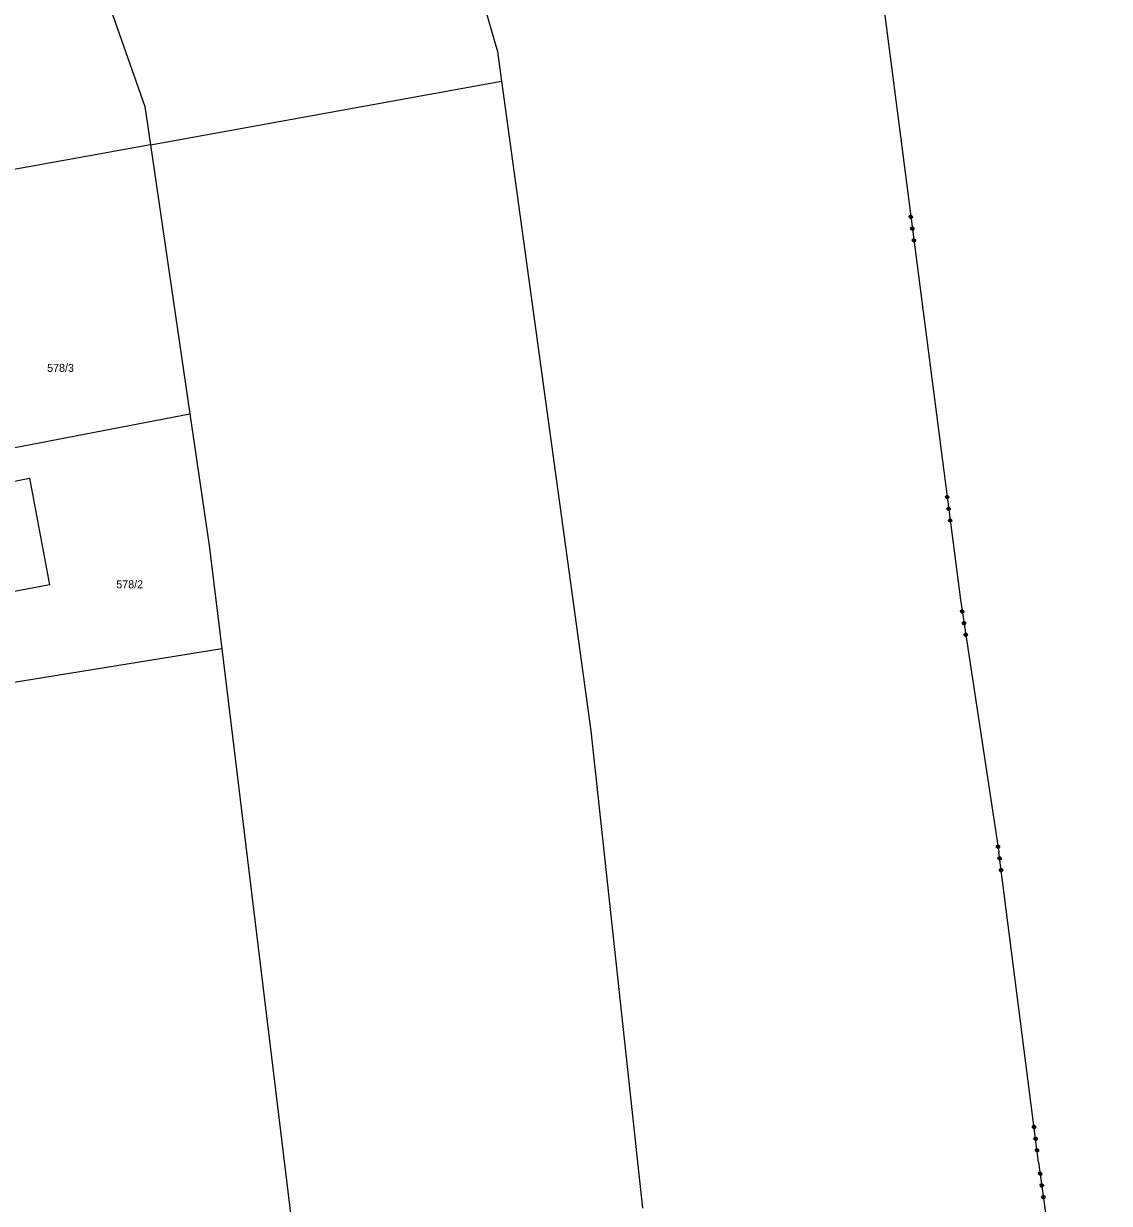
# Model space of a CAD drawing. Extents: x -757994 to -755874, y -1047691 to -1046119.
# Drawn here: x -756280.8 to -756165.6, y -1047301.2 to -1047176 of the extents above; entities that cross this region are included whole.
import ezdxf

# ---------------------------------------------------------------- set-up
doc = ezdxf.new("R2010")
doc.units = 0
doc.layers.add('katastrální mapa', color=7, linetype='Continuous')

msp = doc.modelspace()

# ---------------------------------------------------------------- linework, layer by layer
at = {"layer": 'katastrální mapa'}
for p, q in [((-756190.66, -1047165.51), (-756181.38, -1047237.16)), ((-756273.16, -1047169.96), (-756267.97, -1047184.79)), ((-756233.22, -1047169.59), (-756230.54, -1047178.96)), ((-756230.54, -1047178.96), (-756230.11, -1047182.09)), ((-756267.38, -1047188.84), (-756230.11, -1047182.09)), ((-756230.11, -1047182.09), (-756220.62, -1047251.06)), ((-756267.97, -1047184.79), (-756267.38, -1047188.84)), ((-756267.38, -1047188.84), (-756306.5, -1047195.93)), ((-756267.38, -1047188.84), (-756263.18, -1047217.41)), ((-756305.29, -1047225.5), (-756263.18, -1047217.41)), ((-756263.18, -1047217.41), (-756261.14, -1047231.38)), ((-756299.85, -1047228), (-756280.23, -1047224.25)), ((-756280.23, -1047224.25), (-756278.1, -1047235.56)), ((-756261.14, -1047231.38), (-756259.8, -1047242.35)), ((-756278.1, -1047235.56), (-756283.5, -1047236.59)), ((-756181.38, -1047237.16), (-756177.32, -1047263.94)), ((-756259.8, -1047242.35), (-756308.79, -1047250.3)), ((-756259.8, -1047242.35), (-756246.38, -1047352.4)), ((-756220.62, -1047251.06), (-756215.14, -1047301.74)), ((-756173.09, -1047296.85), (-756177.32, -1047263.94)), ((-756173.09, -1047296.85), (-756165.57, -1047351.39))]:
    msp.add_line(p, q, dxfattribs=at)
for points in [[(-756186.48, -1047196.55), (-756186.56, -1047196.65), (-756186.69, -1047196.67), (-756186.8, -1047196.59), (-756186.82, -1047196.45), (-756186.74, -1047196.35), (-756186.6, -1047196.33), (-756186.5, -1047196.41), (-756186.48, -1047196.55), (-756186.5, -1047196.55), (-756186.51, -1047196.43), (-756186.56, -1047196.4), (-756186.53, -1047196.6), (-756186.57, -1047196.63), (-756186.6, -1047196.36), (-756186.64, -1047196.37), (-756186.61, -1047196.63), (-756186.65, -1047196.64), (-756186.68, -1047196.38), (-756186.72, -1047196.38), (-756186.69, -1047196.65), (-756186.73, -1047196.63), (-756186.76, -1047196.41), (-756186.79, -1047196.45), (-756186.78, -1047196.59)], [(-756186.32, -1047197.79), (-756186.4, -1047197.9), (-756186.53, -1047197.91), (-756186.64, -1047197.83), (-756186.66, -1047197.7), (-756186.58, -1047197.59), (-756186.44, -1047197.57), (-756186.34, -1047197.66), (-756186.32, -1047197.79), (-756186.34, -1047197.79), (-756186.35, -1047197.67), (-756186.4, -1047197.63), (-756186.37, -1047197.83), (-756186.41, -1047197.88), (-756186.44, -1047197.6), (-756186.48, -1047197.6), (-756186.45, -1047197.88), (-756186.49, -1047197.89), (-756186.52, -1047197.61), (-756186.56, -1047197.61), (-756186.53, -1047197.89), (-756186.57, -1047197.86), (-756186.6, -1047197.66), (-756186.63, -1047197.7), (-756186.62, -1047197.82)], [(-756186.16, -1047199.03), (-756186.24, -1047199.14), (-756186.37, -1047199.16), (-756186.48, -1047199.08), (-756186.5, -1047198.94), (-756186.41, -1047198.84), (-756186.28, -1047198.82), (-756186.17, -1047198.9), (-756186.16, -1047199.03), (-756186.18, -1047199.02), (-756186.19, -1047198.9), (-756186.24, -1047198.87), (-756186.21, -1047199.06), (-756186.25, -1047199.11), (-756186.28, -1047198.85), (-756186.32, -1047198.85), (-756186.29, -1047199.11), (-756186.33, -1047199.12), (-756186.36, -1047198.86), (-756186.4, -1047198.86), (-756186.37, -1047199.12), (-756186.41, -1047199.1), (-756186.44, -1047198.9), (-756186.47, -1047198.93), (-756186.46, -1047199.05)], [(-756182.63, -1047226.3), (-756182.71, -1047226.4), (-756182.84, -1047226.42), (-756182.95, -1047226.34), (-756182.97, -1047226.2), (-756182.88, -1047226.1), (-756182.75, -1047226.08), (-756182.64, -1047226.16), (-756182.63, -1047226.3), (-756182.64, -1047226.3), (-756182.66, -1047226.19), (-756182.7, -1047226.15), (-756182.68, -1047226.35), (-756182.72, -1047226.38), (-756182.75, -1047226.12), (-756182.79, -1047226.12), (-756182.76, -1047226.38), (-756182.79, -1047226.39), (-756182.83, -1047226.13), (-756182.87, -1047226.14), (-756182.83, -1047226.4), (-756182.88, -1047226.38), (-756182.9, -1047226.17), (-756182.94, -1047226.21), (-756182.92, -1047226.34)], [(-756182.46, -1047227.54), (-756182.55, -1047227.65), (-756182.68, -1047227.66), (-756182.79, -1047227.58), (-756182.8, -1047227.45), (-756182.72, -1047227.34), (-756182.59, -1047227.33), (-756182.48, -1047227.41), (-756182.46, -1047227.54), (-756182.48, -1047227.54), (-756182.5, -1047227.42), (-756182.55, -1047227.39), (-756182.52, -1047227.58), (-756182.55, -1047227.63), (-756182.59, -1047227.35), (-756182.63, -1047227.36), (-756182.59, -1047227.63), (-756182.63, -1047227.64), (-756182.67, -1047227.36), (-756182.71, -1047227.37), (-756182.67, -1047227.64), (-756182.72, -1047227.61), (-756182.74, -1047227.41), (-756182.78, -1047227.46), (-756182.76, -1047227.57)], [(-756182.3, -1047228.79), (-756182.39, -1047228.89), (-756182.52, -1047228.91), (-756182.63, -1047228.83), (-756182.64, -1047228.69), (-756182.56, -1047228.59), (-756182.43, -1047228.57), (-756182.32, -1047228.65), (-756182.3, -1047228.79), (-756182.33, -1047228.77), (-756182.34, -1047228.65), (-756182.38, -1047228.62), (-756182.36, -1047228.81), (-756182.4, -1047228.86), (-756182.43, -1047228.6), (-756182.47, -1047228.61), (-756182.43, -1047228.86), (-756182.47, -1047228.87), (-756182.51, -1047228.61), (-756182.55, -1047228.61), (-756182.51, -1047228.87), (-756182.56, -1047228.85), (-756182.58, -1047228.65), (-756182.62, -1047228.68), (-756182.6, -1047228.8)], [(-756181.02, -1047238.44), (-756181.1, -1047238.54), (-756181.24, -1047238.56), (-756181.35, -1047238.48), (-756181.37, -1047238.35), (-756181.29, -1047238.24), (-756181.15, -1047238.22), (-756181.05, -1047238.3), (-756181.02, -1047238.44), (-756181.04, -1047238.44), (-756181.06, -1047238.33), (-756181.11, -1047238.29), (-756181.08, -1047238.49), (-756181.11, -1047238.53), (-756181.15, -1047238.26), (-756181.19, -1047238.26), (-756181.15, -1047238.53), (-756181.19, -1047238.54), (-756181.23, -1047238.28), (-756181.27, -1047238.28), (-756181.23, -1047238.54), (-756181.27, -1047238.52), (-756181.31, -1047238.31), (-756181.34, -1047238.35), (-756181.32, -1047238.49)], [(-756180.84, -1047239.68), (-756180.92, -1047239.79), (-756181.05, -1047239.81), (-756181.16, -1047239.73), (-756181.18, -1047239.59), (-756181.1, -1047239.48), (-756180.97, -1047239.46), (-756180.86, -1047239.54), (-756180.84, -1047239.68), (-756180.86, -1047239.68), (-756180.88, -1047239.56), (-756180.92, -1047239.52), (-756180.89, -1047239.72), (-756180.92, -1047239.77), (-756180.97, -1047239.49), (-756181.01, -1047239.5), (-756180.96, -1047239.77), (-756181, -1047239.78), (-756181.05, -1047239.5), (-756181.08, -1047239.51), (-756181.04, -1047239.78), (-756181.09, -1047239.75), (-756181.12, -1047239.55), (-756181.15, -1047239.6), (-756181.13, -1047239.72)], [(-756180.65, -1047240.92), (-756180.73, -1047241.03), (-756180.86, -1047241.05), (-756180.97, -1047240.97), (-756180.99, -1047240.83), (-756180.91, -1047240.72), (-756180.78, -1047240.7), (-756180.67, -1047240.78), (-756180.65, -1047240.92), (-756180.67, -1047240.9), (-756180.69, -1047240.78), (-756180.73, -1047240.76), (-756180.7, -1047240.95), (-756180.74, -1047240.99), (-756180.78, -1047240.74), (-756180.82, -1047240.74), (-756180.78, -1047241), (-756180.82, -1047241), (-756180.86, -1047240.75), (-756180.9, -1047240.75), (-756180.86, -1047241.01), (-756180.9, -1047240.99), (-756180.93, -1047240.79), (-756180.97, -1047240.82), (-756180.95, -1047240.94)], [(-756177.56, -1047263.32), (-756177.48, -1047263.22), (-756177.35, -1047263.2), (-756177.24, -1047263.28), (-756177.22, -1047263.41), (-756177.3, -1047263.52), (-756177.44, -1047263.54), (-756177.54, -1047263.46), (-756177.56, -1047263.32), (-756177.54, -1047263.34), (-756177.52, -1047263.46), (-756177.48, -1047263.48), (-756177.5, -1047263.29), (-756177.47, -1047263.25), (-756177.44, -1047263.51), (-756177.4, -1047263.5), (-756177.43, -1047263.24), (-756177.39, -1047263.24), (-756177.36, -1047263.5), (-756177.32, -1047263.5), (-756177.35, -1047263.24), (-756177.31, -1047263.25), (-756177.28, -1047263.46), (-756177.25, -1047263.43), (-756177.26, -1047263.31)], [(-756177.4, -1047264.57), (-756177.32, -1047264.46), (-756177.18, -1047264.44), (-756177.08, -1047264.52), (-756177.06, -1047264.66), (-756177.14, -1047264.76), (-756177.28, -1047264.78), (-756177.38, -1047264.7), (-756177.4, -1047264.57), (-756177.38, -1047264.57), (-756177.37, -1047264.69), (-756177.32, -1047264.72), (-756177.35, -1047264.52), (-756177.31, -1047264.48), (-756177.28, -1047264.76), (-756177.24, -1047264.75), (-756177.27, -1047264.47), (-756177.23, -1047264.47), (-756177.2, -1047264.75), (-756177.16, -1047264.74), (-756177.19, -1047264.46), (-756177.15, -1047264.5), (-756177.12, -1047264.7), (-756177.09, -1047264.65), (-756177.1, -1047264.53)], [(-756177.24, -1047265.81), (-756177.16, -1047265.7), (-756177.02, -1047265.69), (-756176.92, -1047265.77), (-756176.9, -1047265.9), (-756176.98, -1047266.01), (-756177.12, -1047266.03), (-756177.22, -1047265.94), (-756177.24, -1047265.81), (-756177.22, -1047265.8), (-756177.21, -1047265.92), (-756177.16, -1047265.96), (-756177.19, -1047265.76), (-756177.15, -1047265.72), (-756177.12, -1047265.99), (-756177.08, -1047265.99), (-756177.11, -1047265.72), (-756177.07, -1047265.71), (-756177.04, -1047265.98), (-756177, -1047265.97), (-756177.03, -1047265.71), (-756176.99, -1047265.73), (-756176.96, -1047265.94), (-756176.93, -1047265.9), (-756176.94, -1047265.76)], [(-756173.74, -1047293.08), (-756173.65, -1047292.97), (-756173.52, -1047292.95), (-756173.41, -1047293.04), (-756173.4, -1047293.17), (-756173.48, -1047293.28), (-756173.61, -1047293.29), (-756173.72, -1047293.21), (-756173.74, -1047293.08), (-756173.71, -1047293.09), (-756173.7, -1047293.21), (-756173.66, -1047293.24), (-756173.68, -1047293.05), (-756173.65, -1047293), (-756173.61, -1047293.26), (-756173.57, -1047293.26), (-756173.61, -1047293), (-756173.57, -1047292.99), (-756173.53, -1047293.25), (-756173.49, -1047293.25), (-756173.53, -1047292.99), (-756173.48, -1047293.01), (-756173.46, -1047293.21), (-756173.42, -1047293.18), (-756173.44, -1047293.06)], [(-756173.58, -1047294.32), (-756173.49, -1047294.22), (-756173.36, -1047294.2), (-756173.25, -1047294.28), (-756173.24, -1047294.41), (-756173.32, -1047294.52), (-756173.45, -1047294.54), (-756173.56, -1047294.46), (-756173.58, -1047294.32), (-756173.56, -1047294.32), (-756173.54, -1047294.44), (-756173.5, -1047294.48), (-756173.52, -1047294.28), (-756173.49, -1047294.23), (-756173.45, -1047294.51), (-756173.41, -1047294.51), (-756173.45, -1047294.23), (-756173.41, -1047294.22), (-756173.37, -1047294.5), (-756173.33, -1047294.5), (-756173.37, -1047294.22), (-756173.32, -1047294.25), (-756173.3, -1047294.45), (-756173.26, -1047294.41), (-756173.28, -1047294.29)], [(-756173.42, -1047295.57), (-756173.33, -1047295.46), (-756173.2, -1047295.44), (-756173.09, -1047295.52), (-756173.08, -1047295.66), (-756173.16, -1047295.76), (-756173.29, -1047295.78), (-756173.4, -1047295.7), (-756173.42, -1047295.57), (-756173.4, -1047295.56), (-756173.38, -1047295.68), (-756173.34, -1047295.71), (-756173.36, -1047295.51), (-756173.33, -1047295.48), (-756173.29, -1047295.75), (-756173.25, -1047295.74), (-756173.29, -1047295.48), (-756173.25, -1047295.47), (-756173.21, -1047295.73), (-756173.17, -1047295.73), (-756173.21, -1047295.46), (-756173.16, -1047295.48), (-756173.14, -1047295.7), (-756173.1, -1047295.66), (-756173.12, -1047295.52)], [(-756172.75, -1047298.13), (-756172.83, -1047298.24), (-756172.97, -1047298.26), (-756173.07, -1047298.18), (-756173.09, -1047298.04), (-756173.01, -1047297.93), (-756172.88, -1047297.92), (-756172.77, -1047298), (-756172.75, -1047298.13), (-756172.77, -1047298.14), (-756172.79, -1047298.02), (-756172.83, -1047297.99), (-756172.8, -1047298.18), (-756172.84, -1047298.22), (-756172.88, -1047297.95), (-756172.92, -1047297.96), (-756172.88, -1047298.22), (-756172.92, -1047298.23), (-756172.96, -1047297.97), (-756173, -1047297.97), (-756172.96, -1047298.24), (-756173, -1047298.22), (-756173.03, -1047298), (-756173.07, -1047298.04), (-756173.05, -1047298.18)], [(-756172.58, -1047299.37), (-756172.66, -1047299.48), (-756172.8, -1047299.5), (-756172.9, -1047299.42), (-756172.92, -1047299.28), (-756172.84, -1047299.18), (-756172.71, -1047299.16), (-756172.6, -1047299.24), (-756172.58, -1047299.37), (-756172.6, -1047299.37), (-756172.62, -1047299.25), (-756172.66, -1047299.22), (-756172.64, -1047299.42), (-756172.67, -1047299.46), (-756172.71, -1047299.18), (-756172.75, -1047299.19), (-756172.71, -1047299.47), (-756172.75, -1047299.47), (-756172.79, -1047299.2), (-756172.83, -1047299.2), (-756172.79, -1047299.48), (-756172.83, -1047299.44), (-756172.86, -1047299.25), (-756172.89, -1047299.29), (-756172.88, -1047299.41)], [(-756172.41, -1047300.62), (-756172.49, -1047300.72), (-756172.62, -1047300.74), (-756172.73, -1047300.66), (-756172.75, -1047300.53), (-756172.67, -1047300.42), (-756172.54, -1047300.4), (-756172.43, -1047300.48), (-756172.41, -1047300.62), (-756172.43, -1047300.6), (-756172.45, -1047300.48), (-756172.49, -1047300.46), (-756172.47, -1047300.65), (-756172.5, -1047300.69), (-756172.54, -1047300.43), (-756172.58, -1047300.44), (-756172.54, -1047300.7), (-756172.58, -1047300.7), (-756172.62, -1047300.44), (-756172.66, -1047300.44), (-756172.62, -1047300.7), (-756172.66, -1047300.69), (-756172.69, -1047300.48), (-756172.73, -1047300.51), (-756172.71, -1047300.63)]]:
    msp.add_lwpolyline(points, dxfattribs=at)

# ---------------------------------------------------------------- texts
for s, p in [('578/3', (-756278.34, -1047212.96)), ('578/2', (-756271, -1047235.94))]:
    msp.add_text(s, height=0.85, dxfattribs=at).set_placement(p)

doc.saveas('drawing.dxf')
